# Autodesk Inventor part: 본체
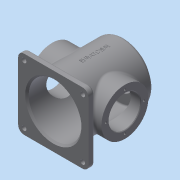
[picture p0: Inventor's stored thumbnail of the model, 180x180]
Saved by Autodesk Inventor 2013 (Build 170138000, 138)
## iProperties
Created: 2015-10
Part Number: 본체
Material: 일반
Document SubType Name: Modeling
Designer: Administrator
Density: 1 g/cm^3
Author: Administrator
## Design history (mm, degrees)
sketch "스케치1"
  geometry: L1 (-60, 60)-(60, 60); L2 (60, 60)-(60, -60); L3 (60, -60)-(-60, -60); L4 (-60, -60)-(-60, 60); 1 further point
  constraints: 8 end point, 2 parallel, 1 horizontal, 1 perpendicular
  dimensions: "d0" = 120 distance of L1.start L1.end; "d2" = 120 distance of L3.end L1.start
extrude "돌출1" new body sketch "스케치1" distance "d3" = 10; taper "d4" = 0 deg
sketch "스케치2"
  geometry: C1 r 50 at (0, 0); 1 further point
  constraints: 1 centre point, 1 coincident
  dimensions: "d5" = 100 diameter of C1
extrude "돌출2" join sketch "스케치2" distance "d7" = 110; taper "d8" = 0 deg
sketch "스케치3"
  geometry: C1 r 50 at (0, 0) reference; C2 r 40 at (0, 0)
  constraints: 1 centre point, 1 coincident
  dimensions: "d9" = 80 diameter of C2
extrude "돌출3" join sketch "스케치3" distance "d11" = 5; taper "d12" = 0 deg
sketch "스케치4"
  geometry: C1 r 40 at (0, 0) reference; C2 r 27 at (0, 0)
  constraints: 1 centre point, 1 coincident
  dimensions: "d13" = 54 diameter of C2
extrude "돌출4" cut sketch "스케치4" distance "d15" = 13; taper "d16" = 0 deg
sketch "스케치5"
  geometry: C1 r 45 at (0, 0); 1 further point
  constraints: 1 centre point, 1 coincident
  dimensions: "d17" = 90 diameter of C1
extrude "돌출5" cut sketch "스케치5" distance "d19" = 112; taper "d20" = 0 deg
node "작업 평면1"
sketch "스케치6"
  geometry: L1 (0, 0)-(60, 0); C1 r 40 at (60, 0)
  constraints: 2 end point, 1 centre point, 1 coincident, 1 horizontal
  dimensions: "d22" = 60 distance of L1.start L1.end; "d23" = 80 diameter of C1
extrude "돌출6" join sketch "스케치6" stored distance "d24" = 112; taper "d25" = 0 deg
node "작업 평면2"
sketch "스케치7"
  geometry: L1 (0, 0)-(60, 0); C1 r 40 at (60, 0)
  constraints: 2 end point, 1 centre point, 1 coincident, 1 horizontal
  dimensions: "d27" = 60 distance of L1.start L1.end
extrude "돌출7" join sketch "스케치7" stored distance "d29" = 112; taper "d30" = 0 deg
sketch "스케치8"
  geometry: C1 r 40 at (0, 0) reference; C2 r 27 at (0, 0); 1 further point
  constraints: 1 centre point, 1 coincident
  dimensions: "d31" = 54 diameter of C2
extrude "돌출8" cut sketch "스케치8" stored distance "d33" = 112; taper "d34" = 0 deg
sketch "스케치9"
  geometry: C1 r 40 at (0, 0) reference; C2 r 27 at (0, 0); 1 further point
  constraints: 1 centre point, 1 coincident
  dimensions: "d35" = 54 diameter of C2
extrude "돌출9" cut sketch "스케치9" stored distance "d37" = 112; taper "d38" = 0 deg
sketch "스케치10"
  geometry: C1 r 4 at (-50, 50); C2 r 4 at (50, 50); C3 r 4 at (50, -50); C4 r 4 at (-50, -50)
  constraints: 4 centre point
  dimensions: "d44" = 4 radius of C1; "d45" = 4 radius of C2; "d46" = 4 radius of C3; "d47" = 4 radius of C4
extrude "돌출10" cut sketch "스케치10" stored distance "d48" = 112; taper "d49" = 0 deg
sketch "스케치11"
  geometry: 6 further points
  constraints: 1 coincident
hole "구멍1" sketch "스케치11" at (0, 32.5), (-32.5, 0), (32.5, 0), (0, -32.5) diameter "d51" = 3.242; stored, may be unused: countersink angle "d55" = 82 deg, drill point angle "d57" = 118 deg; dims "d52" = 8, "d53" = 3.023, "d54" = 2, "d56" = 10
sketch "스케치12"
  geometry: 5 further points
hole "구멍2" sketch "스케치12" at (0, 32.5), (-32.5, 0), (0, -32.5), (32.5, 0) diameter "d60" = 3.242; stored, may be unused: countersink angle "d64" = 82 deg, drill point angle "d66" = 118 deg; dims "d61" = 8, "d62" = 3.023, "d63" = 2, "d65" = 10
sketch "스케치13"
  geometry: 4 further points
hole "구멍3" sketch "스케치13" at (-22.981, 22.981), (-22.981, -22.981), (22.981, -22.981), (22.981, 22.981) diameter "d70" = 3.242; stored, may be unused: countersink angle "d74" = 82 deg, drill point angle "d76" = 118 deg; dims "d71" = 8, "d72" = 3.023, "d73" = 2, "d75" = 10
chamfer "모따기1" distance "d77" = 3; stored, may be unused: second distance "d78" = 2, angle "d79" = 45 deg
fillet "모깎기1" dims "d80" = 3, "d81" = 5, "d82" = 3
fillet "모깎기3" dims "d84" = 10, "d85" = 3
chamfer "모따기2" distance "d86" = 1; stored, may be unused: second distance "d87" = 2, angle "d88" = 45 deg
chamfer "모따기3" distance "d89" = 1; stored, may be unused: second distance "d90" = 2, angle "d91" = 45 deg
chamfer "모따기4" distance "d92" = 1; stored, may be unused: second distance "d93" = 2, angle "d94" = 45 deg
node "작업 평면4"
sketch "스케치15"
  geometry: 2 further points
  constraints: 1 other
feature "엠보싱1" sketch "스케치15" dims "d0" = 120, "d2" = 120, "d13" = 54, "d99" = 0.5, "d100" = 0
node "솔리드1"
other parameters: "d21" = 62, "d26" = -62
